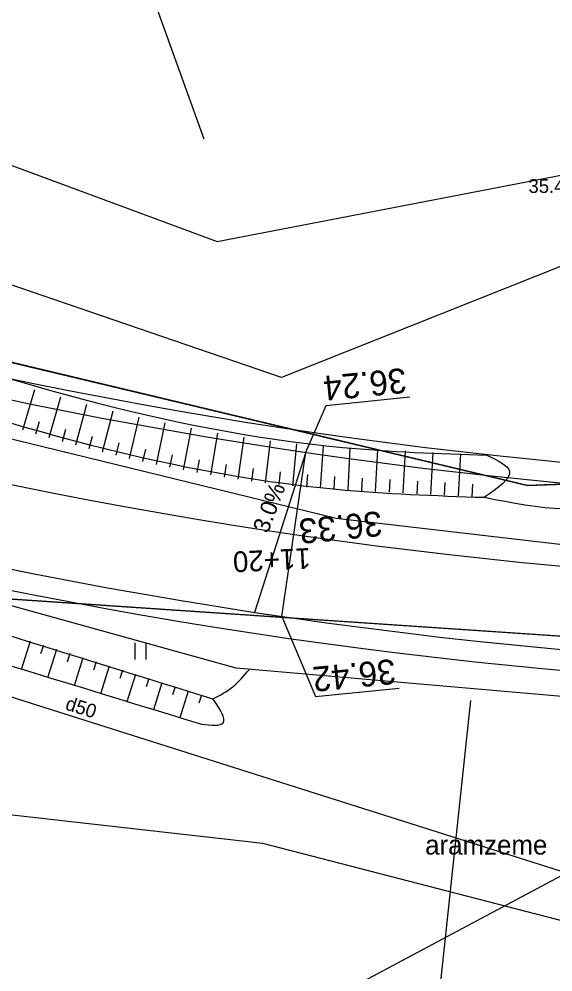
# Model space of a CAD drawing. Extents: x 469981 to 472086, y 246785 to 247785.
# Drawn here: x 470971.09 to 470990.4, y 247171.2 to 247205.68 of the extents above; entities that cross this region are included whole.
import ezdxf

# ---------------------------------------------------------------- set-up
doc = ezdxf.new("R2010")
doc.units = 0
for name, color, linetype in [('0_922', 7, 'Continuous'), ('0_Asfalta_mala', 7, 'Continuous'), ('0_Asfalta_Nomale', 7, 'Continuous'), ('0_Ruut_Braukt', 7, 'Continuous'), ('0_Ruut_nomale', 7, 'Continuous'), ('0_vertikals', 7, 'Continuous'), ('0_vertkals_cipari', 7, 'Continuous'), ('21', 7, 'Continuous'), ('5_patagas', 7, 'Continuous'), ('6_piketaza', 7, 'Continuous'), ('CELI_CMAL_####_####_#', 7, 'Continuous'), ('DREN_VADP_####_####_#', 7, 'Continuous'), ('DREN_VADP_####_TKST_#', 7, 'Continuous'), ('DREN_VADP_KLKT_####_#', 7, 'Continuous'), ('RAMI_UZMR_####_####_#', 7, 'Continuous'), ('RELJ_AATZ_####_TKST_#', 7, 'Continuous'), ('RELJ_NOGA_####_####_#', 7, 'Continuous'), ('RELJ_NOGL_####_####_#', 7, 'Continuous'), ('ROBZ_PROJ_####_####_#', 7, 'Continuous'), ('ROBZ_UZMR_####_####_#', 7, 'Continuous'), ('TERT_ELEM_####_####_#', 7, 'Continuous'), ('TERT_IZMT_####_TKST_#', 7, 'Continuous'), ('TERT_KONT_####_####_#', 7, 'Continuous')]:
    doc.layers.add(name, color=color, linetype=linetype)

msp = doc.modelspace()

# ---------------------------------------------------------------- linework, layer by layer
at = {"layer": '0_922'}
msp.add_arc((471007.123, 247365.136), 180, 250.3373, 277.44649, dxfattribs=at)
at = {"layer": '0_Asfalta_mala'}
for radius in [177, 183]:
    msp.add_arc((471007.123, 247365.136), radius, 250.3373, 277.44649, dxfattribs=at)
at = {"layer": '0_Asfalta_Nomale'}
for radius in [176.25, 183.75]:
    msp.add_arc((471007.123, 247365.136), radius, 250.3373, 277.44649, dxfattribs=at)
at = {"layer": '0_Ruut_Braukt'}
for radius in [177, 183]:
    msp.add_arc((471007.123, 247365.136), radius, 250.3373, 277.44649, dxfattribs=at)
at = {"layer": '0_Ruut_nomale'}
for radius, start, end in [(176.25, 250.3373, 277.44649), (177, 250.33757, 277.4462), (183, 250.33757, 277.44649), (183.75, 250.3373, 277.44649)]:
    msp.add_arc((471007.123, 247365.136), radius, start, end, dxfattribs=at)
at = {"layer": '0_vertikals'}
for p, q in [((470982.198, 247191.704), (470985.229, 247192.008)), ((470981.46, 247190.006), (470982.198, 247191.704)), ((470980.591, 247184.069), (470981.809, 247181.174)), ((470981.809, 247181.174), (470984.84, 247181.478))]:
    msp.add_line(p, q, dxfattribs=at)
msp.add_lwpolyline([(470981.46, 247190.006), (470979.601, 247184.216), (470980.591, 247184.069)], close=True, dxfattribs=at)
at = {"layer": '21'}
msp.add_arc((471007.123, 247365.136), 180, 250.3373, 277.44649, dxfattribs=at)
at = {"layer": '5_patagas'}
msp.add_lwpolyline([(470987.421, 247181.03), (470985.293, 247161.143)], dxfattribs=at)
at = {"layer": '6_piketaza'}
msp.add_lwpolyline([(470980.989, 247186.79), (470981.062, 247187.285)], dxfattribs=at)
at = {"layer": 'CELI_CMAL_####_####_#'}
for points in [[(470887.869, 247219.351), (470907.988, 247212.254), (470934.743, 247202.499), (470962.898, 247192.42), (470982.559, 247187.627), (470994.5, 247186.238), (471002.099, 247186.455), (471014.161, 247188.048), (471038.308, 247191.645)], [(471015.923, 247182.598), (470992.26, 247181.035), (470978.943, 247182.194), (470959.244, 247187.66), (470932.844, 247196.714), (470906.026, 247206.836), (470881.196, 247215.092)]]:
    msp.add_lwpolyline(points, dxfattribs=at)
at = {"layer": 'DREN_VADP_####_####_#'}
for points in [[(470845.346, 247220.939), (470990.896, 247174.789)], [(470971.511, 247218.733), (470977.768, 247201.349)]]:
    msp.add_lwpolyline(points, dxfattribs=at)
at = {"layer": 'DREN_VADP_KLKT_####_#'}
for points in [[(470998.012, 247199.651), (470980.588, 247192.708), (470867.536, 247231.459)], [(470950.722, 247153.356), (470963.906, 247160.39), (470978.685, 247168.275), (470990.896, 247174.789), (471002.512, 247177.058), (471004.882, 247177.521)]]:
    msp.add_lwpolyline(points, dxfattribs=at)
at = {"layer": 'RAMI_UZMR_####_####_#'}
for points in [[(470560.64, 247175.144), (470793.366, 247232.231), (470822.25, 247233), (470855.497, 247231.608), (470869.75, 247235.5), (470872.288, 247238.827), (470875.523, 247240.24), (470882.387, 247236.327), (470885.36, 247235.904), (470900.348, 247222.872), (470947.872, 247208.875), (470978.25, 247197.629), (470994.287, 247200.731), (471010.572, 247199.465), (471044.448, 247201.846)], [(471016.707, 247172.079), (470997.217, 247171.376), (470979.902, 247175.851), (470953.212, 247178.863), (470866.8, 247207.896), (470847.133, 247208.95), (470818.512, 247207.896), (470793.929, 247204.557), (470730.787, 247190.475), (470682.857, 247179.693), (470601.924, 247155.957)]]:
    msp.add_lwpolyline(points, dxfattribs=at)
at = {"layer": 'RELJ_NOGA_####_####_#'}
for p, q in [((470971.219, 247190.816), (470971.654, 247192.284)), ((470972.179, 247190.538), (470972.596, 247192.012)), ((470973.143, 247190.272), (470973.54, 247191.753)), ((470974.111, 247190.02), (470974.488, 247191.507)), ((470971.698, 247190.675), (470971.827, 247191.117)), ((470975.083, 247189.785), (470975.433, 247191.279)), ((470972.661, 247190.403), (470972.784, 247190.846)), ((470976.059, 247189.567), (470976.378, 247191.068)), ((470977.039, 247189.368), (470977.329, 247190.875)), ((470973.626, 247190.144), (470973.741, 247190.59)), ((470978.022, 247189.188), (470978.282, 247190.701)), ((470979.01, 247189.031), (470979.232, 247190.549)), ((470980.001, 247188.896), (470980.187, 247190.418)), ((470974.596, 247189.901), (470974.705, 247190.348)), ((470975.57, 247189.674), (470975.672, 247190.123)), ((470980.995, 247188.787), (470981.142, 247190.31)), ((470981.991, 247188.703), (470982.098, 247190.227)), ((470982.989, 247188.644), (470983.072, 247190.168)), ((470983.988, 247188.59), (470984.07, 247190.113)), ((470984.986, 247188.536), (470985.069, 247190.059)), ((470976.548, 247189.465), (470976.64, 247189.916)), ((470977.53, 247189.275), (470977.612, 247189.728)), ((470985.985, 247188.482), (470986.067, 247190.005)), ((470986.984, 247188.428), (470987.066, 247189.951)), ((470978.516, 247189.107), (470978.587, 247189.562)), ((470979.505, 247188.961), (470979.567, 247189.417)), ((470980.497, 247188.838), (470980.548, 247189.295)), ((470981.493, 247188.741), (470981.531, 247189.199)), ((470982.49, 247188.671), (470982.516, 247189.129)), ((470983.489, 247188.617), (470983.513, 247189.074)), ((470984.487, 247188.563), (470984.512, 247189.02)), ((470985.486, 247188.509), (470985.51, 247188.966)), ((470986.484, 247188.455), (470986.509, 247188.912)), ((470987.483, 247188.401), (470987.508, 247188.858)), ((470971.489, 247183.172), (470971.163, 247182.138)), ((470971.489, 247183.172), (470971.163, 247182.138)), ((470971.966, 247183.022), (470971.869, 247182.713)), ((470971.966, 247183.022), (470971.869, 247182.713)), ((470972.443, 247182.871), (470972.12, 247181.849)), ((470972.443, 247182.871), (470972.12, 247181.849)), ((470972.92, 247182.721), (470972.823, 247182.416)), ((470972.92, 247182.721), (470972.823, 247182.416)), ((470973.396, 247182.571), (470973.078, 247181.56)), ((470973.396, 247182.571), (470973.078, 247181.56)), ((470973.873, 247182.42), (470973.778, 247182.119)), ((470973.873, 247182.42), (470973.778, 247182.119)), ((470974.35, 247182.27), (470974.035, 247181.27)), ((470974.35, 247182.27), (470974.035, 247181.27)), ((470974.827, 247182.119), (470974.733, 247181.821)), ((470974.827, 247182.119), (470974.733, 247181.821)), ((470975.304, 247181.969), (470974.992, 247180.981)), ((470975.304, 247181.969), (470974.992, 247180.981)), ((470975.781, 247181.819), (470975.688, 247181.524)), ((470975.781, 247181.819), (470975.688, 247181.524)), ((470976.257, 247181.668), (470975.95, 247180.692)), ((470976.257, 247181.668), (470975.95, 247180.692)), ((470976.734, 247181.518), (470976.642, 247181.227)), ((470976.734, 247181.518), (470976.642, 247181.227)), ((470977.211, 247181.367), (470976.907, 247180.403)), ((470977.211, 247181.367), (470976.907, 247180.403)), ((470977.688, 247181.217), (470977.597, 247180.929)), ((470977.688, 247181.217), (470977.597, 247180.929))]:
    msp.add_line(p, q, dxfattribs=at)
for points in [[(470889.682, 247220.928), (470894.215, 247218.482), (470908.262, 247213.396), (470935.093, 247203.884), (470963.658, 247193.357), (470982.569, 247188.667), (470987.924, 247188.377)], [(470443.762, 247118.331), (470443.88, 247120.814), (470444.471, 247122.233), (470445.96, 247123.747), (470447.74, 247124.344), (470466.701, 247130.323), (470490.205, 247137.037), (470509.522, 247142.633), (470536.42, 247149.583), (470558.637, 247154.955), (470585.403, 247162.504), (470607.875, 247168.231), (470633.412, 247175.414), (470656.062, 247180.759), (470680.788, 247187.471), (470708.074, 247193.923), (470734.191, 247200.317), (470761.697, 247206.456), (470789.773, 247212.754), (470817.257, 247216.179), (470830.019, 247217.144), (470848.586, 247217.569), (470861.752, 247217.476), (470881.066, 247214.264), (470905.336, 247205.96), (470932.738, 247196.11), (470958.906, 247187.141), (470978.102, 247181.086)]]:
    msp.add_spline(points, degree=3, dxfattribs=at)
at = {"layer": 'RELJ_NOGL_####_####_#'}
for points in [[(470890.406, 247222.27), (470894.84, 247219.878), (470908.777, 247214.832), (470935.612, 247205.319), (470964.107, 247194.817), (470982.796, 247190.182), (470988.007, 247189.901)], [(470444.636, 247118.184), (470444.802, 247120.028), (470444.991, 247120.926), (470445.558, 247121.73), (470446.408, 247122.251), (470448.872, 247122.621), (470466.486, 247128.526), (470490.665, 247135.792), (470509.603, 247140.94), (470537.55, 247147.945), (470558.966, 247153.542), (470586.086, 247160.934), (470607.922, 247166.842), (470634.241, 247173.648), (470681.28, 247185.658), (470708.292, 247192.117), (470734.878, 247198.699), (470761.457, 247204.922), (470790.498, 247211.068), (470817.148, 247213.701), (470830.618, 247215.209), (470848.022, 247215.369), (470862.099, 247215.472), (470880.883, 247212.412), (470904.425, 247203.826), (470932.21, 247193.701), (470958.298, 247186.024), (470977.689, 247180.167)], [(470988.007, 247189.901), (470988.827, 247189.329), (470987.924, 247188.377)], [(470977.689, 247180.167), (470978.474, 247180.215), (470978.102, 247181.086)]]:
    msp.add_spline(points, degree=3, dxfattribs=at)
at = {"layer": 'ROBZ_PROJ_####_####_#'}
for points in [[(470613.752, 247179.765), (470688.303, 247197.106), (470783.692, 247219.293), (470809.088, 247224.67), (470845.751, 247226.447), (470876.169, 247225.296), (470921.641, 247209.731), (470967.353, 247194.084), (470989.48, 247188.802), (471001.509, 247189.266), (471050.609, 247195.379), (471093.674, 247200.298), (471124.72, 247213.54), (471341.261, 247348.2), (471524.883, 247464.852)], [(471398.351, 247372.094), (471346.741, 247338.478), (471133.176, 247205.05), (471108.425, 247194.786), (471087.339, 247189.709), (471023.306, 247181.157), (470962.604, 247185.245), (470905.63, 247205.857), (470878.75, 247214.454), (470852.344, 247217.039), (470815.743, 247215.147), (470778.583, 247209.26), (470718.669, 247194.633), (470636.973, 247175.147), (470468.364, 247124.23), (470431.624, 247112.202), (470396.219, 247097.502), (470371.503, 247083.47), (470275.956, 246992.729), (470152.342, 246907.761), (470066.737, 246851.23)], [(470979.699, 247245.057), (471001.509, 247189.266), (470989.48, 247188.802), (470967.353, 247194.084), (470921.641, 247209.731), (470906.814, 247253.012)]]:
    msp.add_lwpolyline(points, dxfattribs=at)
at = {"layer": 'ROBZ_UZMR_####_####_#'}
msp.add_lwpolyline([(470963.76, 247148.152), (470962.604, 247185.245), (471023.306, 247181.157), (471087.339, 247189.709), (471108.425, 247194.786), (471133.176, 247205.05), (471165.539, 247180.17)], dxfattribs=at)
at = {"layer": 'TERT_ELEM_####_####_#'}
for p, q in [((470975.288, 247182.513), (470975.288, 247183.113)), ((470975.688, 247182.513), (470975.688, 247183.113))]:
    msp.add_line(p, q, dxfattribs=at)
at = {"layer": 'TERT_KONT_####_####_#'}
for points in [[(470987.924, 247188.377), (470992.745, 247188.632), (470993.259, 247191.634), (470991.631, 247198.323)], [(470978.102, 247181.086), (470978.821, 247181.524), (470979.408, 247182.14)]]:
    msp.add_spline(points, degree=3, dxfattribs=at)

# ---------------------------------------------------------------- texts
at = {"layer": '0_vertkals_cipari'}
for s, height, rotation, p in [('36.24', 0.9, 185.7316, (470985.053, 247193.062)), ('3.0%', 0.5993, 69.2101, (470980.088, 247187.048)), ('36.33', 0.9, 185.7316, (470984.175, 247187.884)), ('36.42', 0.9, 185.7316, (470984.664, 247182.532))]:
    msp.add_text(s, height=height, rotation=rotation, dxfattribs=at).set_placement(p)
at = {"layer": '6_piketaza'}
msp.add_text('11+20', height=0.75, rotation=182.8045, dxfattribs=at).set_placement((470981.621, 247186.548))
at = {"layer": 'DREN_VADP_####_TKST_#'}
msp.add_text('d50', height=0.5, rotation=342.4077, dxfattribs=at).set_placement((470972.728, 247180.707))
at = {"layer": 'RELJ_AATZ_####_TKST_#'}
msp.add_text('35.41', height=0.5, dxfattribs=at).set_placement((470989.517, 247199.39))
at = {"layer": 'TERT_IZMT_####_TKST_#'}
msp.add_text('aramzeme', height=0.7, dxfattribs=at).set_placement((470985.779, 247175.452))

doc.saveas('drawing.dxf')
